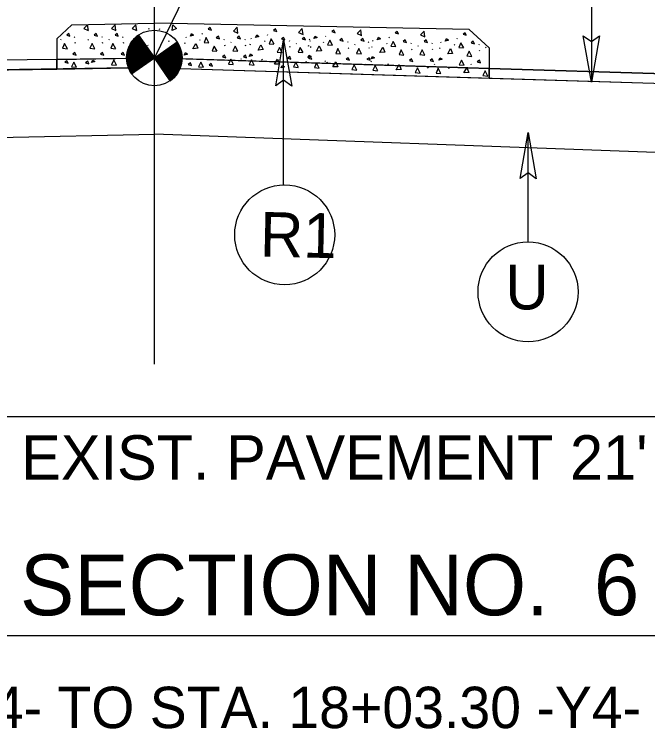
# Model space of a CAD drawing. Extents: x 2176156 to 2177167, y 76401 to 76644.
# Drawn here: x 2176318.14 to 2176334.56, y 76544.04 to 76562.57 of the extents above; entities that cross this region are included whole.
import ezdxf

# ---------------------------------------------------------------- set-up
doc = ezdxf.new("R2010")
doc.units = 0
for name, color, linetype in [('Exist Building Metal Canopy', 7, 'Continuous'), ('Exist Roads Change in Surface', 7, 'Continuous'), ('Exist Roads Curbs', 7, 'Continuous'), ('Exist Roads Soil', 7, 'Continuous'), ('Exist Structure Minor Culvert Topo', 7, 'Continuous'), ('Exist Vegetation Woods Line', 7, 'Continuous'), ('Model Boundary Lines Text', 7, 'Continuous'), ('Old_Level_3', 7, 'Continuous'), ('Prop North Arrow NAD83 for Plan Sheets CELL', 7, 'Continuous'), ('Sheet Plan CELL', 7, 'Continuous')]:
    doc.layers.add(name, color=color, linetype=linetype)

msp = doc.modelspace()

# ---------------------------------------------------------------- linework, layer by layer
at = {"layer": 'Exist Roads Change in Surface'}
for p, q in [((2176321.635, 76562.179), (2176321.625, 76562.203)), ((2176321.902, 76562.179), (2176321.913, 76562.203)), ((2176323.015, 76562.075), (2176323.004, 76562.059)), ((2176319.346, 76561.923), (2176319.336, 76561.907)), ((2176319.705, 76561.99), (2176319.694, 76561.974)), ((2176320.059, 76561.923), (2176320.048, 76561.907)), ((2176320.418, 76561.99), (2176320.407, 76561.974)), ((2176320.598, 76561.923), (2176320.588, 76561.907)), ((2176320.957, 76561.99), (2176320.947, 76561.974)), ((2176321.357, 76562.034), (2176321.769, 76561.442)), ((2176321.393, 76561.87), (2176321.382, 76561.894)), ((2176322.145, 76561.87), (2176322.156, 76561.894)), ((2176322.581, 76561.99), (2176322.591, 76561.974)), ((2176322.94, 76561.923), (2176322.95, 76561.907)), ((2176323.583, 76561.923), (2176323.572, 76561.907)), ((2176324.122, 76561.923), (2176324.112, 76561.907)), ((2176324.269, 76561.957), (2176324.28, 76561.941)), ((2176324.628, 76561.889), (2176324.638, 76561.873)), ((2176324.703, 76562.042), (2176324.692, 76562.026)), ((2176325.271, 76561.889), (2176325.26, 76561.873)), ((2176325.784, 76561.926), (2176325.795, 76561.91)), ((2176325.81, 76561.889), (2176325.8, 76561.873)), ((2176326.218, 76562.011), (2176326.208, 76561.995)), ((2176327.426, 76561.893), (2176327.437, 76561.877)), ((2176327.86, 76561.979), (2176327.849, 76561.963)), ((2176329.618, 76561.943), (2176329.607, 76561.927)), ((2176319.725, 76561.815), (2176319.715, 76561.839)), ((2176320.438, 76561.815), (2176320.427, 76561.839)), ((2176320.977, 76561.815), (2176320.967, 76561.839)), ((2176321.609, 76561.754), (2176321.598, 76561.777)), ((2176321.769, 76561.442), (2176322.361, 76561.854)), ((2176321.929, 76561.754), (2176321.94, 76561.777)), ((2176322.56, 76561.815), (2176322.571, 76561.839)), ((2176323.603, 76561.747), (2176323.592, 76561.771)), ((2176323.763, 76561.855), (2176323.753, 76561.839)), ((2176324.142, 76561.747), (2176324.132, 76561.771)), ((2176324.249, 76561.781), (2176324.259, 76561.805)), ((2176325.291, 76561.714), (2176325.281, 76561.738)), ((2176325.452, 76561.821), (2176325.441, 76561.805)), ((2176325.764, 76561.751), (2176325.775, 76561.775)), ((2176325.831, 76561.714), (2176325.82, 76561.738)), ((2176326.143, 76561.858), (2176326.154, 76561.843)), ((2176326.787, 76561.859), (2176326.776, 76561.843)), ((2176326.807, 76561.683), (2176326.796, 76561.707)), ((2176326.967, 76561.791), (2176326.956, 76561.775)), ((2176327.326, 76561.859), (2176327.315, 76561.843)), ((2176327.346, 76561.683), (2176327.335, 76561.707)), ((2176327.406, 76561.718), (2176327.416, 76561.742)), ((2176327.785, 76561.826), (2176327.795, 76561.81)), ((2176328.428, 76561.826), (2176328.417, 76561.81)), ((2176328.609, 76561.758), (2176328.598, 76561.742)), ((2176328.967, 76561.826), (2176328.957, 76561.81)), ((2176329.164, 76561.683), (2176329.174, 76561.707)), ((2176329.184, 76561.858), (2176329.194, 76561.842)), ((2176329.543, 76561.791), (2176329.553, 76561.775)), ((2176330.186, 76561.791), (2176330.175, 76561.775)), ((2176330.366, 76561.723), (2176330.356, 76561.707)), ((2176321.276, 76561.583), (2176321.265, 76561.567)), ((2176322.262, 76561.583), (2176322.273, 76561.567)), ((2176328.448, 76561.65), (2176328.438, 76561.674)), ((2176328.988, 76561.65), (2176328.977, 76561.674)), ((2176330.206, 76561.615), (2176330.195, 76561.639)), ((2176321.176, 76561.032), (2176321.769, 76561.442)), ((2176321.769, 76561.442), (2176321.176, 76561.032)), ((2176322.181, 76560.85), (2176321.769, 76561.442)), ((2176324.03, 76561.399), (2176324.02, 76561.423)), ((2176324.569, 76561.385), (2176324.559, 76561.409)), ((2176325.716, 76561.322), (2176325.706, 76561.346)), ((2176326.19, 76561.347), (2176326.201, 76561.371)), ((2176326.256, 76561.308), (2176326.246, 76561.332)), ((2176327.394, 76561.356), (2176327.383, 76561.341)), ((2176327.231, 76561.253), (2176327.221, 76561.277)), ((2176327.77, 76561.239), (2176327.76, 76561.263)), ((2176327.83, 76561.272), (2176327.842, 76561.296)), ((2176328.871, 76561.178), (2176328.861, 76561.202)), ((2176329.034, 76561.282), (2176329.023, 76561.266)), ((2176329.41, 76561.164), (2176329.4, 76561.188)), ((2176329.587, 76561.192), (2176329.598, 76561.216)), ((2176329.968, 76561.29), (2176329.979, 76561.274))]:
    msp.add_line(p, q, dxfattribs=at)
for points in [[(2176320.059, 76562.152), (2176320.038, 76562.304), (2176319.943, 76562.206), (2176320.057, 76562.153)], [(2176320.772, 76562.152), (2176320.751, 76562.304), (2176320.655, 76562.206), (2176320.769, 76562.153)], [(2176321.311, 76562.152), (2176321.29, 76562.304), (2176321.195, 76562.206), (2176321.309, 76562.153)], [(2176322.227, 76562.152), (2176322.248, 76562.304), (2176322.343, 76562.206), (2176322.229, 76562.153)], [(2176319.583, 76562.009), (2176319.551, 76562.076), (2176319.498, 76562.036), (2176319.583, 76562.009)], [(2176320.296, 76562.009), (2176320.264, 76562.076), (2176320.21, 76562.036), (2176320.296, 76562.009)], [(2176320.835, 76562.009), (2176320.803, 76562.076), (2176320.75, 76562.036), (2176320.835, 76562.009)], [(2176322.703, 76562.009), (2176322.735, 76562.076), (2176322.788, 76562.036), (2176322.703, 76562.009)], [(2176323.251, 76562.162), (2176323.219, 76562.228), (2176323.166, 76562.188), (2176323.251, 76562.162)], [(2176323.937, 76562.084), (2176323.916, 76562.237), (2176323.82, 76562.138), (2176323.934, 76562.085)], [(2176324.94, 76562.128), (2176324.908, 76562.195), (2176324.854, 76562.155), (2176324.94, 76562.128)], [(2176325.625, 76562.051), (2176325.604, 76562.203), (2176325.509, 76562.104), (2176325.623, 76562.052)], [(2176326.455, 76562.098), (2176326.423, 76562.164), (2176326.37, 76562.124), (2176326.455, 76562.098)], [(2176327.141, 76562.02), (2176327.119, 76562.173), (2176327.024, 76562.074), (2176327.138, 76562.021)], [(2176328.097, 76562.065), (2176328.065, 76562.132), (2176328.011, 76562.092), (2176328.097, 76562.065)], [(2176328.782, 76561.987), (2176328.761, 76562.14), (2176328.666, 76562.041), (2176328.78, 76561.988)], [(2176329.855, 76562.03), (2176329.823, 76562.096), (2176329.769, 76562.056), (2176329.855, 76562.03)], [(2176321.466, 76561.877), (2176321.065, 76561.598)], [(2176321.458, 76561.889), (2176321.07, 76561.619)], [(2176321.45, 76561.901), (2176321.076, 76561.641)], [(2176321.441, 76561.913), (2176321.083, 76561.663)], [(2176321.433, 76561.924), (2176321.09, 76561.686)], [(2176321.425, 76561.936), (2176321.099, 76561.709)], [(2176321.417, 76561.948), (2176321.109, 76561.734)], [(2176321.408, 76561.96), (2176321.122, 76561.761)], [(2176321.4, 76561.972), (2176321.136, 76561.788)], [(2176321.392, 76561.984), (2176321.153, 76561.817)], [(2176321.384, 76561.996), (2176321.172, 76561.848)], [(2176321.376, 76562.007), (2176321.199, 76561.885)], [(2176321.367, 76562.019), (2176321.233, 76561.926)], [(2176321.359, 76562.031), (2176321.295, 76561.986)], [(2176323.185, 76561.834), (2176323.113, 76561.97), (2176323.057, 76561.845), (2176323.182, 76561.834)], [(2176323.461, 76561.941), (2176323.429, 76562.008), (2176323.375, 76561.968), (2176323.461, 76561.941)], [(2176324, 76561.941), (2176323.968, 76562.008), (2176323.915, 76561.968), (2176324, 76561.941)], [(2176324.391, 76561.975), (2176324.423, 76562.042), (2176324.476, 76562.002), (2176324.391, 76561.975)], [(2176324.873, 76561.801), (2176324.801, 76561.937), (2176324.745, 76561.811), (2176324.87, 76561.801)], [(2176325.149, 76561.908), (2176325.117, 76561.974), (2176325.064, 76561.934), (2176325.149, 76561.908)], [(2176325.688, 76561.908), (2176325.656, 76561.974), (2176325.603, 76561.934), (2176325.688, 76561.908)], [(2176325.907, 76561.945), (2176325.939, 76562.011), (2176325.992, 76561.972), (2176325.907, 76561.945)], [(2176326.389, 76561.77), (2176326.317, 76561.906), (2176326.261, 76561.781), (2176326.386, 76561.77)], [(2176326.664, 76561.877), (2176326.632, 76561.944), (2176326.579, 76561.904), (2176326.664, 76561.877)], [(2176327.204, 76561.877), (2176327.172, 76561.944), (2176327.118, 76561.904), (2176327.204, 76561.877)], [(2176327.548, 76561.912), (2176327.58, 76561.979), (2176327.633, 76561.939), (2176327.548, 76561.912)], [(2176328.03, 76561.738), (2176327.958, 76561.873), (2176327.902, 76561.748), (2176328.027, 76561.738)], [(2176328.306, 76561.845), (2176328.274, 76561.911), (2176328.221, 76561.871), (2176328.306, 76561.845)], [(2176328.845, 76561.845), (2176328.813, 76561.911), (2176328.76, 76561.871), (2176328.845, 76561.845)], [(2176329.306, 76561.877), (2176329.338, 76561.943), (2176329.391, 76561.904), (2176329.306, 76561.877)], [(2176330.064, 76561.809), (2176330.032, 76561.876), (2176329.978, 76561.836), (2176330.064, 76561.809)], [(2176319.516, 76561.682), (2176319.444, 76561.817), (2176319.388, 76561.692), (2176319.514, 76561.682)], [(2176320.229, 76561.682), (2176320.157, 76561.817), (2176320.101, 76561.692), (2176320.226, 76561.682)], [(2176320.768, 76561.682), (2176320.697, 76561.817), (2176320.641, 76561.692), (2176320.766, 76561.682)], [(2176321.524, 76561.794), (2176321.048, 76561.463)], [(2176321.532, 76561.783), (2176321.048, 76561.446)], [(2176321.516, 76561.806), (2176321.049, 76561.481)], [(2176321.54, 76561.771), (2176321.049, 76561.429)], [(2176321.548, 76561.759), (2176321.049, 76561.411)], [(2176321.557, 76561.747), (2176321.049, 76561.394)], [(2176321.507, 76561.818), (2176321.05, 76561.5)], [(2176321.565, 76561.735), (2176321.051, 76561.377)], [(2176321.499, 76561.83), (2176321.052, 76561.519)], [(2176321.573, 76561.723), (2176321.053, 76561.361)], [(2176321.491, 76561.842), (2176321.054, 76561.538)], [(2176321.581, 76561.712), (2176321.054, 76561.345)], [(2176321.483, 76561.854), (2176321.057, 76561.557)], [(2176321.59, 76561.7), (2176321.057, 76561.329)], [(2176321.474, 76561.865), (2176321.06, 76561.577)], [(2176321.598, 76561.688), (2176321.06, 76561.314)], [(2176322.364, 76561.848), (2176322.364, 76561.848), (2176321.773, 76561.437)], [(2176322.373, 76561.837), (2176321.781, 76561.425)], [(2176322.379, 76561.824), (2176321.789, 76561.413)], [(2176322.388, 76561.812), (2176321.797, 76561.401)], [(2176322.395, 76561.799), (2176321.806, 76561.389)], [(2176322.402, 76561.787), (2176321.814, 76561.378)], [(2176322.408, 76561.774), (2176321.822, 76561.366)], [(2176322.415, 76561.761), (2176321.83, 76561.354)], [(2176322.422, 76561.748), (2176321.839, 76561.342)], [(2176322.428, 76561.735), (2176321.847, 76561.33)], [(2176322.434, 76561.721), (2176321.855, 76561.318)], [(2176322.439, 76561.707), (2176321.863, 76561.307)], [(2176322.445, 76561.694), (2176321.871, 76561.295)], [(2176322.769, 76561.682), (2176322.841, 76561.817), (2176322.897, 76561.692), (2176322.772, 76561.682)], [(2176323.394, 76561.614), (2176323.322, 76561.75), (2176323.266, 76561.625), (2176323.391, 76561.614)], [(2176323.933, 76561.614), (2176323.861, 76561.75), (2176323.806, 76561.625), (2176323.931, 76561.614)], [(2176324.458, 76561.648), (2176324.53, 76561.784), (2176324.586, 76561.658), (2176324.46, 76561.648)], [(2176325.082, 76561.58), (2176325.01, 76561.716), (2176324.954, 76561.591), (2176325.08, 76561.58)], [(2176325.622, 76561.58), (2176325.55, 76561.716), (2176325.494, 76561.591), (2176325.619, 76561.58)], [(2176325.973, 76561.618), (2176326.045, 76561.753), (2176326.101, 76561.628), (2176325.976, 76561.618)], [(2176327.615, 76561.585), (2176327.687, 76561.721), (2176327.743, 76561.595), (2176327.617, 76561.585)], [(2176329.788, 76561.702), (2176329.716, 76561.838), (2176329.66, 76561.713), (2176329.785, 76561.702)], [(2176319.744, 76561.514), (2176319.712, 76561.58), (2176319.659, 76561.54), (2176319.744, 76561.514)], [(2176320.457, 76561.514), (2176320.425, 76561.58), (2176320.371, 76561.54), (2176320.457, 76561.514)], [(2176320.996, 76561.514), (2176320.964, 76561.58), (2176320.911, 76561.54), (2176320.996, 76561.514)], [(2176321.606, 76561.676), (2176321.063, 76561.298)], [(2176321.614, 76561.664), (2176321.066, 76561.283)], [(2176321.623, 76561.652), (2176321.069, 76561.267)], [(2176321.631, 76561.641), (2176321.073, 76561.253)], [(2176321.639, 76561.629), (2176321.078, 76561.238)], [(2176321.647, 76561.617), (2176321.082, 76561.223)], [(2176321.656, 76561.605), (2176321.088, 76561.21)], [(2176321.664, 76561.593), (2176321.092, 76561.195)], [(2176321.672, 76561.581), (2176321.097, 76561.182)], [(2176321.68, 76561.569), (2176321.103, 76561.168)], [(2176321.688, 76561.558), (2176321.109, 76561.154)], [(2176321.697, 76561.546), (2176321.114, 76561.141)], [(2176321.705, 76561.534), (2176321.121, 76561.128)], [(2176321.713, 76561.522), (2176321.127, 76561.114)], [(2176321.721, 76561.51), (2176321.134, 76561.101)], [(2176322.449, 76561.679), (2176321.88, 76561.283)], [(2176322.455, 76561.665), (2176321.888, 76561.271)], [(2176322.459, 76561.651), (2176321.896, 76561.259)], [(2176322.463, 76561.636), (2176321.904, 76561.247)], [(2176322.468, 76561.622), (2176321.913, 76561.236)], [(2176322.47, 76561.606), (2176321.921, 76561.224)], [(2176322.473, 76561.591), (2176321.929, 76561.212)], [(2176322.476, 76561.575), (2176321.937, 76561.2)], [(2176322.479, 76561.56), (2176321.946, 76561.188)], [(2176322.482, 76561.544), (2176321.954, 76561.176)], [(2176322.484, 76561.528), (2176321.962, 76561.165)], [(2176322.486, 76561.511), (2176321.97, 76561.153)], [(2176322.542, 76561.514), (2176322.574, 76561.58), (2176322.627, 76561.54), (2176322.542, 76561.514)], [(2176323.622, 76561.446), (2176323.59, 76561.513), (2176323.536, 76561.473), (2176323.622, 76561.446)], [(2176324.161, 76561.446), (2176324.129, 76561.513), (2176324.076, 76561.473), (2176324.161, 76561.446)], [(2176324.23, 76561.48), (2176324.262, 76561.547), (2176324.315, 76561.507), (2176324.23, 76561.48)], [(2176325.746, 76561.45), (2176325.778, 76561.516), (2176325.831, 76561.476), (2176325.746, 76561.45)], [(2176326.598, 76561.55), (2176326.526, 76561.686), (2176326.47, 76561.561), (2176326.595, 76561.55)], [(2176327.137, 76561.55), (2176327.065, 76561.686), (2176327.009, 76561.561), (2176327.134, 76561.55)], [(2176328.239, 76561.517), (2176328.167, 76561.653), (2176328.111, 76561.528), (2176328.237, 76561.517)], [(2176328.779, 76561.517), (2176328.707, 76561.653), (2176328.651, 76561.528), (2176328.776, 76561.517)], [(2176329.373, 76561.55), (2176329.444, 76561.685), (2176329.5, 76561.56), (2176329.375, 76561.55)], [(2176329.997, 76561.482), (2176329.925, 76561.618), (2176329.869, 76561.493), (2176329.994, 76561.482)], [(2176319.533, 76561.303), (2176319.503, 76561.371), (2176319.448, 76561.332), (2176319.533, 76561.303)], [(2176319.752, 76561.2), (2176319.68, 76561.336), (2176319.624, 76561.211), (2176319.749, 76561.2)], [(2176320.072, 76561.289), (2176320.042, 76561.357), (2176319.988, 76561.318), (2176320.072, 76561.289)], [(2176320.142, 76561.321), (2176320.176, 76561.387), (2176320.228, 76561.346), (2176320.142, 76561.321)], [(2176320.787, 76561.256), (2176320.716, 76561.392), (2176320.66, 76561.267), (2176320.785, 76561.256)], [(2176321.73, 76561.499), (2176321.141, 76561.089)], [(2176321.738, 76561.487), (2176321.148, 76561.076)], [(2176321.746, 76561.475), (2176321.156, 76561.064)], [(2176321.754, 76561.463), (2176321.163, 76561.051)], [(2176321.763, 76561.451), (2176321.171, 76561.039), (2176321.171, 76561.039)], [(2176322.487, 76561.495), (2176321.979, 76561.141)], [(2176322.489, 76561.479), (2176321.987, 76561.129)], [(2176322.489, 76561.461), (2176321.995, 76561.117)], [(2176322.49, 76561.444), (2176322.003, 76561.105)], [(2176322.489, 76561.426), (2176322.011, 76561.094)], [(2176322.489, 76561.408), (2176322.02, 76561.082)], [(2176322.488, 76561.39), (2176322.028, 76561.07)], [(2176322.486, 76561.371), (2176322.036, 76561.058)], [(2176322.484, 76561.352), (2176322.044, 76561.046)], [(2176322.481, 76561.333), (2176322.053, 76561.034)], [(2176323.044, 76561.2), (2176322.972, 76561.336), (2176322.916, 76561.211), (2176323.041, 76561.2)], [(2176323.817, 76561.271), (2176323.749, 76561.409), (2176323.69, 76561.285), (2176323.815, 76561.271)], [(2176324.357, 76561.257), (2176324.288, 76561.395), (2176324.229, 76561.271), (2176324.354, 76561.257)], [(2176324.882, 76561.277), (2176324.957, 76561.411), (2176325.01, 76561.285), (2176324.884, 76561.277)], [(2176325.31, 76561.413), (2176325.278, 76561.479), (2176325.225, 76561.439), (2176325.31, 76561.413)], [(2176325.504, 76561.194), (2176325.436, 76561.332), (2176325.377, 76561.208), (2176325.501, 76561.194)], [(2176325.849, 76561.413), (2176325.817, 76561.479), (2176325.764, 76561.439), (2176325.849, 76561.413)], [(2176326.043, 76561.18), (2176325.975, 76561.318), (2176325.916, 76561.194), (2176326.041, 76561.18)], [(2176326.396, 76561.208), (2176326.471, 76561.342), (2176326.524, 76561.216), (2176326.398, 76561.208)], [(2176326.825, 76561.382), (2176326.793, 76561.449), (2176326.74, 76561.409), (2176326.825, 76561.382)], [(2176327.365, 76561.382), (2176327.333, 76561.449), (2176327.28, 76561.409), (2176327.365, 76561.382)], [(2176327.387, 76561.417), (2176327.419, 76561.483), (2176327.472, 76561.443), (2176327.387, 76561.417)], [(2176328.467, 76561.349), (2176328.435, 76561.416), (2176328.382, 76561.376), (2176328.467, 76561.349)], [(2176329.006, 76561.349), (2176328.974, 76561.416), (2176328.921, 76561.376), (2176329.006, 76561.349)], [(2176329.145, 76561.382), (2176329.177, 76561.448), (2176329.23, 76561.408), (2176329.145, 76561.382)], [(2176329.799, 76561.252), (2176329.727, 76561.387), (2176329.671, 76561.262), (2176329.796, 76561.252)], [(2176330.225, 76561.314), (2176330.193, 76561.381), (2176330.139, 76561.341), (2176330.225, 76561.314)], [(2176322.478, 76561.313), (2176322.061, 76561.023)], [(2176322.474, 76561.293), (2176322.069, 76561.011)], [(2176322.469, 76561.272), (2176322.077, 76560.999)], [(2176322.463, 76561.25), (2176322.086, 76560.987)], [(2176322.457, 76561.228), (2176322.094, 76560.975)], [(2176322.449, 76561.205), (2176322.102, 76560.963)], [(2176322.44, 76561.181), (2176322.11, 76560.952)], [(2176322.43, 76561.157), (2176322.119, 76560.94)], [(2176322.419, 76561.131), (2176322.127, 76560.928)], [(2176322.734, 76561.244), (2176322.704, 76561.312), (2176322.649, 76561.273), (2176322.734, 76561.244)], [(2176323.273, 76561.23), (2176323.243, 76561.298), (2176323.189, 76561.259), (2176323.273, 76561.23)], [(2176325.053, 76561.184), (2176325.086, 76561.25), (2176325.139, 76561.209), (2176325.053, 76561.184)], [(2176327.018, 76561.125), (2176326.95, 76561.263), (2176326.891, 76561.139), (2176327.016, 76561.125)], [(2176327.558, 76561.111), (2176327.489, 76561.249), (2176327.43, 76561.125), (2176327.555, 76561.111)], [(2176328.036, 76561.134), (2176328.111, 76561.268), (2176328.164, 76561.141), (2176328.039, 76561.134)], [(2176328.659, 76561.05), (2176328.59, 76561.188), (2176328.531, 76561.064), (2176328.656, 76561.05)], [(2176329.198, 76561.036), (2176329.129, 76561.174), (2176329.07, 76561.05), (2176329.195, 76561.036)], [(2176329.792, 76561.054), (2176329.868, 76561.188), (2176329.92, 76561.061), (2176329.795, 76561.053)], [(2176322.406, 76561.105), (2176322.135, 76560.916)], [(2176322.389, 76561.075), (2176322.143, 76560.904)], [(2176322.37, 76561.044), (2176322.151, 76560.892)], [(2176322.345, 76561.01), (2176322.16, 76560.881)], [(2176322.313, 76560.969), (2176322.168, 76560.869)], [(2176330.415, 76560.97), (2176330.346, 76561.108), (2176330.287, 76560.984), (2176330.412, 76560.97)], [(2176322.26, 76560.915), (2176322.176, 76560.857)]]:
    msp.add_lwpolyline(points, dxfattribs=at)
msp.add_circle((2176321.769, 76561.443), 0.721, dxfattribs=at)
for start, end in [(124.8249, 214.8249), (304.8249, 34.8249)]:
    msp.add_arc((2176321.769, 76561.443), 0.721, start, end, dxfattribs=at)
at = {"layer": 'Exist Roads Curbs'}
for p, q in [((2176319.239, 76561.404), (2176307.239, 76561.226)), ((2176319.239, 76561.404), (2176307.239, 76561.226)), ((2176319.239, 76561.404), (2176321.769, 76561.442)), ((2176321.048, 76561.431), (2176319.239, 76561.404)), ((2176319.239, 76561.154), (2176319.239, 76561.404)), ((2176319.239, 76561.404), (2176319.239, 76561.154)), ((2176321.049, 76561.394), (2176321.049, 76561.394)), ((2176321.054, 76561.345), (2176321.055, 76561.345)), ((2176321.769, 76561.442), (2176330.444, 76561.171)), ((2176322.481, 76561.333), (2176322.481, 76561.333)), ((2176322.488, 76561.39), (2176322.488, 76561.39)), ((2176330.444, 76561.171), (2176322.489, 76561.42)), ((2176322.489, 76561.408), (2176322.489, 76561.408)), ((2176321.097, 76561.182), (2176306.983, 76560.972)), ((2176319.239, 76561.154), (2176321.097, 76561.182)), ((2176321.069, 76561.267), (2176321.069, 76561.267)), ((2176321.073, 76561.253), (2176321.073, 76561.253)), ((2176321.082, 76561.223), (2176321.082, 76561.223)), ((2176322.436, 76561.171), (2176342.704, 76560.539)), ((2176322.436, 76561.171), (2176330.444, 76560.921)), ((2176322.449, 76561.205), (2176322.449, 76561.205)), ((2176322.457, 76561.228), (2176322.457, 76561.228)), ((2176322.469, 76561.272), (2176322.469, 76561.271)), ((2176322.474, 76561.293), (2176322.474, 76561.292)), ((2176322.478, 76561.313), (2176322.478, 76561.313)), ((2176330.444, 76561.171), (2176342.444, 76560.797)), ((2176342.444, 76560.797), (2176330.444, 76561.171)), ((2176330.444, 76561.171), (2176330.444, 76560.921)), ((2176330.444, 76560.921), (2176330.444, 76561.171)), ((2176330.444, 76560.921), (2176338.626, 76560.666))]:
    msp.add_line(p, q, dxfattribs=at)
for points in [[(2176321.049, 76561.394), (2176321.049, 76561.394)], [(2176321.055, 76561.345), (2176321.054, 76561.345)], [(2176322.481, 76561.333), (2176322.481, 76561.333)], [(2176322.488, 76561.39), (2176322.488, 76561.39)], [(2176322.489, 76561.408), (2176322.489, 76561.408)], [(2176307.25, 76560.736), (2176308.813, 76560.76), (2176309.529, 76560.77), (2176310.927, 76560.791), (2176312.319, 76560.812), (2176312.319, 76561.052), (2176319.239, 76561.154)], [(2176321.07, 76561.267), (2176321.069, 76561.267)], [(2176321.073, 76561.253), (2176321.073, 76561.253)], [(2176321.082, 76561.223), (2176321.082, 76561.223)], [(2176322.449, 76561.205), (2176322.449, 76561.205)], [(2176322.457, 76561.228), (2176322.457, 76561.228)], [(2176322.469, 76561.272), (2176322.469, 76561.272)], [(2176322.474, 76561.293), (2176322.474, 76561.293)], [(2176322.478, 76561.313), (2176322.478, 76561.313)], [(2176330.444, 76560.921), (2176330.444, 76560.921)]]:
    msp.add_lwpolyline(points, dxfattribs=at)
for start, end in [(180.9136, 182.5146), (182.5146, 183.8761), (183.8895, 187.8094), (187.8245, 190.3336), (349.5984, 351.2038), (351.2196, 352.7539), (352.7539, 355.7778), (355.8127, 357.2394), (357.2652, 358.1523), (190.3336, 191.5882), (191.5882, 194.0754), (194.0907, 195.2968), (195.2976, 197.7127), (197.7154, 201.2126), (337.8613, 340.731), (340.7368, 342.6429), (342.646, 346.2404), (346.2648, 347.9455), (347.9775, 349.598)]:
    msp.add_arc((2176321.769, 76561.443), 0.721, start, end, dxfattribs=at)
at = {"layer": 'Exist Roads Soil'}
for p, q in [((2176319.239, 76561.936), (2176319.634, 76562.299)), ((2176319.634, 76562.299), (2176321.769, 76562.342)), ((2176329.927, 76562.179), (2176321.769, 76562.342)), ((2176330.444, 76561.703), (2176329.927, 76562.179)), ((2176319.239, 76561.936), (2176319.239, 76561.154)), ((2176330.444, 76561.703), (2176330.444, 76560.921))]:
    msp.add_line(p, q, dxfattribs=at)
at = {"layer": 'Model Boundary Lines Text'}
msp.add_line((2176308.108, 76546.457), (2176335.43, 76546.457), dxfattribs=at)
at = {"layer": 'Old_Level_3'}
for p, q in [((2176321.769, 76553.503), (2176321.769, 76572.796)), ((2176312.317, 76552.143), (2176338.626, 76552.143))]:
    msp.add_line(p, q, dxfattribs=at)
at = {"layer": 'Prop North Arrow NAD83 for Plan Sheets CELL'}
for p, q in [((2176324.492, 76567.05), (2176321.769, 76561.442)), ((2176333.1, 76563.616), (2176333.1, 76560.812)), ((2176325.12, 76558.151), (2176325.12, 76561.916)), ((2176331.454, 76556.669), (2176331.454, 76559.511))]:
    msp.add_line(p, q, dxfattribs=at)
for points in [[(2176324.914, 76560.716), (2176325.12, 76561.916), (2176325.334, 76560.71), (2176325.12, 76560.863)], [(2176333.307, 76562.012), (2176333.1, 76560.812), (2176332.887, 76562.019), (2176333.1, 76561.866)], [(2176331.248, 76558.311), (2176331.454, 76559.511), (2176331.668, 76558.305), (2176331.454, 76558.458)]]:
    msp.add_lwpolyline(points, close=True, dxfattribs=at)
for centre in [(2176325.147, 76556.855), (2176331.454, 76555.373)]:
    msp.add_circle(centre, 1.296, dxfattribs=at)
at = {"layer": 'Sheet Plan CELL'}
for p in [(2176312.319, 76559.266), (2176338.626, 76558.851)]:
    msp.add_line(p, (2176321.769, 76559.462), dxfattribs=at)

# ---------------------------------------------------------------- texts
at = {"layer": 'Exist Building Metal Canopy'}
msp.add_text('TYPICAL SECTION NO.  6', height=1.5766, rotation=0, dxfattribs=at).set_placement((2176308.914, 76546.985))
at = {"layer": 'Exist Structure Minor Culvert Topo'}
msp.add_text("EXIST. PAVEMENT 21'", height=1.15334, dxfattribs=at).set_placement((2176318.316, 76550.502))
at = {"layer": 'Exist Vegetation Woods Line'}
msp.add_text('STA. 14+50.00 -Y4- TO STA. 18+03.30 -Y4-', height=1.0742, dxfattribs=at).set_placement((2176306.121, 76544.058))
at = {"layer": 'Prop North Arrow NAD83 for Plan Sheets CELL'}
for s, rotation, p in [('R1', 358.8249, (2176324.499, 76556.289)), ('U', 0.0003, (2176330.868, 76554.919))]:
    msp.add_text(s, height=1.16, rotation=rotation, dxfattribs=at).set_placement(p)

doc.saveas('drawing.dxf')
